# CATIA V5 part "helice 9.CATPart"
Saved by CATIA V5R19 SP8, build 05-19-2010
Part number: helice 9
Bounding box of the stored display mesh (mm): x -17.321 to 17.321, y -30 to 195, z -10 to 20
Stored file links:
  G:\EU_thinkMotion\CFAO_2010\MMS_groupe2\MMS_groupe2\A reprendre\splanchenault\Planchenault\helice 9.CATPart
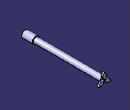
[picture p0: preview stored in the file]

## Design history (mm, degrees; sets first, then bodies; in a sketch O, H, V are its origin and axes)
Body1 (main body)
  Sketch1 on xy-plane, origin (0, 0, 0), H (1, 0, 0), V (0, 1, 0)
    line L1 (0, 0) -> (0, -30)
    line L2 (0, -30) -> (-10, -30)
    line L3 (-10, -30) -> (-10, 0)
    line L4 (-10, 0) -> (-7.5, 0)
    line L5 (-7.5, 0) -> (-7.5, 190)
    line L6 (-7.5, 190) -> (0, 190)
    point P6 (0, 190)
    line L7 (0, 190) -> (0, 0)
    length L6 = 7.5
    length L2 = 10
    length L5 = 190
    distance L4 H = 0
    length L3 = 30
    vertical: L1 V, L3 V, L5 V, L7 V
    horizontal: L2 H, L4 H, L6 H
    coincidence: P6 V
  Shaft1: profile Sketch1, axis Sketch1.L7, angle 360
  Sketch2 on face of Shaft1 from Sketch1.L6, origin (0, 190, 0), H (-1, 0, 0), V (0, 0, 1)
    construction line L1 (27.3861, -15.8114) -> (-27.3861, 15.8114)
    axis line L2 (-31.225, -18.0278) -> (31.225, 18.0278)
    line L3 (0, 0) -> (5.7735, 10)
    point P5 (5.7735, 10)
    line L4 (5.7735, 10) -> (0, 20)
    point P6 (0, 20)
    line L5 (0, 20) -> (-5.7735, 10)
    point P7 (-5.7735, 10)
    line L6 (-5.7735, 10) -> (0, 0)
    point P8 (-11.547, 0)
    point P9 (-17.3205, -10)
    line L7 (-17.3205, -10) -> (-11.547, 0)
    point P10 (-5.7735, -10)
    line L8 (-5.7735, -10) -> (-17.3205, -10)
    point P11 (0, 0)
    line L9 (0, 0) -> (-5.7735, -10)
    line L10 (-11.547, 0) -> (0, 0)
    point P12 (5.7735, -10)
    point P13 (17.3205, -10)
    line L11 (17.3205, -10) -> (5.7735, -10)
    point P14 (11.547, 0)
    line L12 (11.547, 0) -> (17.3205, -10)
    point P15 (0, 0)
    line L13 (0, 0) -> (11.547, 0)
    line L14 (5.7735, -10) -> (0, 0)
    angle L1 V = 60
    angle L2 V = 60
    perpendicularity: L3 L1, L4 L2
    coincidence: P6 V, O P11, O P15, P11 P15
    parallelism: L5 L3, L6 L4
    symmetry: P7 P8 L1, P6 P9 L1, L5 L7 L1, P5 P10 L1, L4 L8 L1, O P11 L1, L3 L9 L1, L6 L10 L1, P7 P12 L2, P6 P13 L2, L5 L11 L2, P5 P14 L2, L4 L12 L2, O P15 L2, L3 L13 L2, L6 L14 L2
  Pad1: profile Sketch2, direction (0, 1, 0), length 5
